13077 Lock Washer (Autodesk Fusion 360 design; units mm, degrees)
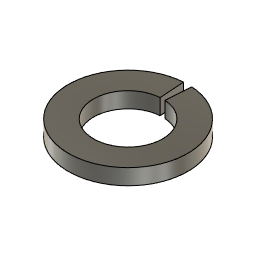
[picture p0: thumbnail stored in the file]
sketch "Main Profile" plane through (0, 0, 0) normal (0, 0, 1) x axis (1, 0, 0)
  line L1 (0, 7.5406) -> (0, 0)
  line L2 (-0.3045, 4.355) -> (0, 0)
  line L3 (0.3045, 4.355) -> (0, 0)
  line L4 (0.526, 7.5223) -> (0.3045, 4.355)
  line L5 (-0.526, 7.5223) -> (-0.3045, 4.355)
  circle C1 centre (0, 0) radius 4.3656
  circle C2 centre (0, 0) radius 7.5406
  point P1 (0, 0)
  point P2 (0, 0)
  point P3 (0, 0)
  point P4 (0, 0)
  point P5 (0, 7.5406)
  point P6 (0, 0)
  point P7 (-0.3045, 4.355)
  point P8 (0, 0)
  point P9 (0.3045, 4.355)
  point P10 (0.526, 7.5223)
  point P11 (-0.526, 7.5223)
  coincident P1 P2
  concentric C1 C2
  coincident P3 P4
  coincident C2 P5
  vertical L1
  coincident P3 P6
  coincident C1 P7
  coincident P3 P8
  coincident C1 P9
  coincident C2 P10
  parallel L3 L4
  coincident C2 P11
  parallel L2 L5
  symmetric L1 L4 L5
  dimension "d1" diameter C1 = 8.7313 (= "( 11 / 32 ) * 1 in")
  dimension "d2" diameter C2 = 15.0812 (= "( 19 / 32 ) * 1 in")
  dimension "d3" angle L4 L5 = 8
extrude "Extrude1" new body sketch "Main Profile" profile of C1 C2 L4 L5 along normal blind 1.9844 (= "( 5 / 64 ) * 1 in") bodies "13077 Lock Washer"
named bodies: "13077 Lock Washer"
